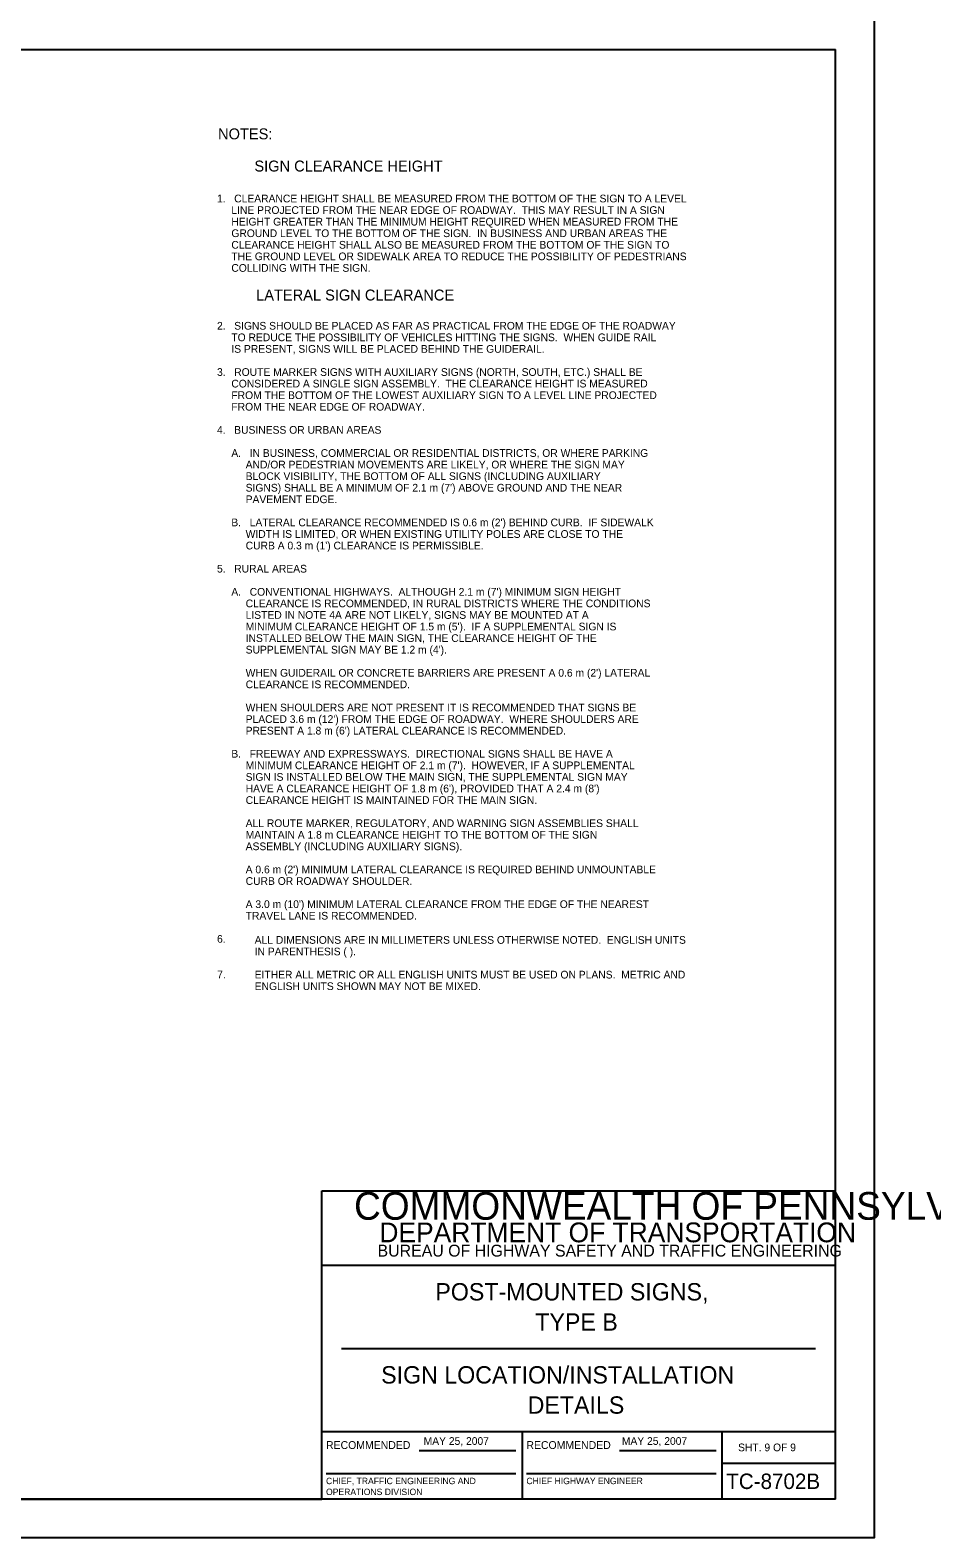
# Model space of a CAD drawing. Extents: x 644358 to 648627, y 294594 to 295782.
# Drawn here: x 647394 to 647745, y 294594 to 295180 of the extents above; entities that cross this region are included whole.
import ezdxf

# ---------------------------------------------------------------- set-up
doc = ezdxf.new("R2010")
doc.units = 0
for name, color, linetype in [('1', 7, 'Continuous'), ('2', 7, 'Continuous'), ('4', 7, 'Continuous'), ('PLT-BNDY', 7, 'Continuous')]:
    doc.layers.add(name, color=color, linetype=linetype)

msp = doc.modelspace()

# ---------------------------------------------------------------- linework, layer by layer
at = {"layer": '1'}
for p, q in [((646921.31, 295172.63), (647707.31, 295172.63)), ((647707.31, 294608.63), (647707.31, 295172.63)), ((647507.31, 294608.63), (647507.31, 294728.63)), ((647507.31, 294728.63), (647707.31, 294728.63)), ((647707.31, 294699.63), (647507.31, 294699.63)), ((647515.06, 294667.31), (647699.56, 294667.31)), ((647507.31, 294635), (647707.31, 294635)), ((647585.31, 294635), (647585.31, 294608.63)), ((647663.19, 294608.63), (647663.19, 294635)), ((647545.24, 294627.57), (647582.87, 294627.57)), ((647623.24, 294627.57), (647660.87, 294627.57)), ((647663.19, 294622.63), (647707.31, 294622.63)), ((647508.99, 294618.68), (647582.87, 294618.68)), ((647586.99, 294618.68), (647660.87, 294618.68)), ((647707.31, 294608.63), (646921.31, 294608.63)), ((646921.31, 294608.63), (647507.31, 294608.63))]:
    msp.add_line(p, q, dxfattribs=at)
at = {"layer": 'PLT-BNDY'}
msp.add_lwpolyline([(646881.31, 295187.63), (647722.31, 295187.63), (647722.31, 294593.63), (646881.31, 294593.63)], close=True, dxfattribs=at)

# ---------------------------------------------------------------- texts
at = {"layer": '1'}
for s, height, p in [('COMMONWEALTH OF PENNSYLVANIA', 10.7828, (647519.9, 294717.36)), ('DEPARTMENT OF TRANSPORTATION', 7.6837, (647529.76, 294708.61)), ('BUREAU OF HIGHWAY SAFETY AND TRAFFIC ENGINEERING', 4.6253, (647529.04, 294703.04)), ('POST-MOUNTED SIGNS,', 6.75, (647551.54, 294685.97)), ('TYPE B', 6.75, (647590.45, 294674.22)), ('SIGN LOCATION/INSTALLATION', 6.75, (647530.45, 294653.66)), ('DETAILS', 6.75, (647587.47, 294641.91)), ('RECOMMENDED', 3.048, (647508.99, 294628.2)), ('RECOMMENDED', 3.048, (647586.99, 294628.2)), ('SHT. 9 OF 9', 3, (647669.39, 294627.31)), ('CHIEF, TRAFFIC ENGINEERING AND', 2.5, (647508.99, 294614.51)), ('CHIEF HIGHWAY ENGINEER', 2.5, (647586.99, 294614.51)), ('TC-8702B', 6, (647664.77, 294612.63)), ('OPERATIONS DIVISION', 2.5, (647508.99, 294610.26))]:
    msp.add_text(s, height=height, dxfattribs=at).set_placement(p)
at = {"layer": '2'}
for s, height, p in [('NOTES:', 4.25, (647466.97, 295137.65)), ('1.   CLEARANCE HEIGHT SHALL BE MEASURED FROM THE BOTTOM OF THE SIGN TO A LEVEL', 3, (647466.56, 295113.13)), ('     LINE PROJECTED FROM THE NEAR EDGE OF ROADWAY.  THIS MAY RESULT IN A SIGN', 3, (647466.56, 295108.63)), ('     HEIGHT GREATER THAN THE MINIMUM HEIGHT REQUIRED WHEN MEASURED FROM THE', 3, (647466.56, 295104.13)), ('     GROUND LEVEL TO THE BOTTOM OF THE SIGN.  IN BUSINESS AND URBAN AREAS THE', 3, (647466.56, 295099.63)), ('     CLEARANCE HEIGHT SHALL ALSO BE MEASURED FROM THE BOTTOM OF THE SIGN TO', 3, (647466.56, 295095.13)), ('     THE GROUND LEVEL OR SIDEWALK AREA TO REDUCE THE POSSIBILITY OF PEDESTRIANS', 3, (647466.56, 295090.63)), ('     COLLIDING WITH THE SIGN.', 3, (647466.56, 295086.13)), ('2.   SIGNS SHOULD BE PLACED AS FAR AS PRACTICAL FROM THE EDGE OF THE ROADWAY', 3, (647466.56, 295063.63)), ('     TO REDUCE THE POSSIBILITY OF VEHICLES HITTING THE SIGNS.  WHEN GUIDE RAIL', 3, (647466.56, 295059.13)), ('     IS PRESENT, SIGNS WILL BE PLACED BEHIND THE GUIDERAIL.                                            ', 3, (647466.56, 295054.63)), ('3.   ROUTE MARKER SIGNS WITH AUXILIARY SIGNS (NORTH, SOUTH, ETC.) SHALL BE  ', 3, (647466.56, 295045.63)), ('     CONSIDERED A SINGLE SIGN ASSEMBLY.  THE CLEARANCE HEIGHT IS MEASURED  ', 3, (647466.56, 295041.13)), ('     FROM THE BOTTOM OF THE LOWEST AUXILIARY SIGN TO A LEVEL LINE PROJECTED ', 3, (647466.56, 295036.63)), ('     FROM THE NEAR EDGE OF ROADWAY.                                                 ', 3, (647466.56, 295032.13)), ('4.   BUSINESS OR URBAN AREAS                                               ', 3, (647466.56, 295023.13)), ('     A.   IN BUSINESS, COMMERCIAL OR RESIDENTIAL DISTRICTS, OR WHERE PARKING', 3, (647466.56, 295014.13)), ('          AND/OR PEDESTRIAN MOVEMENTS ARE LIKELY, OR WHERE THE SIGN MAY    ', 3, (647466.56, 295009.63)), ("          SIGNS) SHALL BE A MINIMUM OF 2.1 m (7') ABOVE GROUND AND THE NEAR    ", 3, (647466.56, 295000.63)), ('          BLOCK VISIBILITY, THE BOTTOM OF ALL SIGNS (INCLUDING AUXILIARY   ', 3, (647466.56, 295005.13)), ('          PAVEMENT EDGE.                                                   ', 3, (647466.56, 294996.13)), ("     B.   LATERAL CLEARANCE RECOMMENDED IS 0.6 m (2') BEHIND CURB.  IF SIDEWALK", 3, (647466.56, 294987.13)), ('          WIDTH IS LIMITED, OR WHEN EXISTING UTILITY POLES ARE CLOSE TO THE', 3, (647466.56, 294982.63)), ("          CURB A 0.3 m (1') CLEARANCE IS PERMISSIBLE.                          ", 3, (647466.56, 294978.13)), ('5.   RURAL AREAS                                                           ', 3, (647466.56, 294969.13)), ("     A.   CONVENTIONAL HIGHWAYS.  ALTHOUGH 2.1 m (7') MINIMUM SIGN HEIGHT      ", 3, (647466.56, 294960.13)), ('          CLEARANCE IS RECOMMENDED, IN RURAL DISTRICTS WHERE THE CONDITIONS', 3, (647466.56, 294955.63)), ('          LISTED IN NOTE 4A ARE NOT LIKELY, SIGNS MAY BE MOUNTED AT A      ', 3, (647466.56, 294951.13)), ("          MINIMUM CLEARANCE HEIGHT OF 1.5 m (5').  IF A SUPPLEMENTAL SIGN IS   ", 3, (647466.56, 294946.63)), ('          INSTALLED BELOW THE MAIN SIGN, THE CLEARANCE HEIGHT OF THE       ', 3, (647466.56, 294942.13)), ("          SUPPLEMENTAL SIGN MAY BE 1.2 m (4').                                 ", 3, (647466.56, 294937.63)), ("          WHEN GUIDERAIL OR CONCRETE BARRIERS ARE PRESENT A 0.6 m (2') LATERAL ", 3, (647466.56, 294928.63)), ('          CLEARANCE IS RECOMMENDED.                                        ', 3, (647466.56, 294924.13)), ('          WHEN SHOULDERS ARE NOT PRESENT IT IS RECOMMENDED THAT SIGNS BE   ', 3, (647466.56, 294915.13)), ("          PLACED 3.6 m (12') FROM THE EDGE OF ROADWAY.  WHERE SHOULDERS ARE    ", 3, (647466.56, 294910.63)), ("          PRESENT A 1.8 m (6') LATERAL CLEARANCE IS RECOMMENDED.               ", 3, (647466.56, 294906.13)), ('     B.   FREEWAY AND EXPRESSWAYS.  DIRECTIONAL SIGNS SHALL BE HAVE A', 3, (647466.56, 294897.13)), ("          MINIMUM CLEARANCE HEIGHT OF 2.1 m (7').  HOWEVER, IF A SUPPLEMENTAL", 3, (647466.56, 294892.63)), ('          SIGN IS INSTALLED BELOW THE MAIN SIGN, THE SUPPLEMENTAL SIGN MAY', 3, (647466.56, 294888.13)), ("          HAVE A CLEARANCE HEIGHT OF 1.8 m (6'), PROVIDED THAT A 2.4 m (8')", 3, (647466.56, 294883.63)), ('          CLEARANCE HEIGHT IS MAINTAINED FOR THE MAIN SIGN.                ', 3, (647466.56, 294879.13)), ('          ALL ROUTE MARKER, REGULATORY, AND WARNING SIGN ASSEMBLIES SHALL', 3, (647466.56, 294870.13)), ('          ASSEMBLY (INCLUDING AUXILIARY SIGNS).                           ', 3, (647466.56, 294861.13)), ('          MAINTAIN A 1.8 m CLEARANCE HEIGHT TO THE BOTTOM OF THE SIGN    ', 3, (647466.56, 294865.63)), ("          A 0.6 m (2') MINIMUM LATERAL CLEARANCE IS REQUIRED BEHIND UNMOUNTABLE", 3, (647466.56, 294852.13)), ('          CURB OR ROADWAY SHOULDER.                                       ', 3, (647466.56, 294847.63)), ("          A 3.0 m (10') MINIMUM LATERAL CLEARANCE FROM THE EDGE OF THE NEAREST", 3, (647466.56, 294838.63)), ('          TRAVEL LANE IS RECOMMENDED.', 3, (647466.56, 294834.13)), ('6.   ', 3, (647466.56, 294825.13)), ('MAY 25, 2007', 3, (647546.98, 294629.79)), ('MAY 25, 2007', 3, (647624.14, 294629.79))]:
    msp.add_text(s, height=height, dxfattribs=at).set_placement(p)
at = {"layer": '4'}
for s, height, p in [('SIGN CLEARANCE HEIGHT', 4.25, (647481.11, 295125.14)), ('LATERAL SIGN CLEARANCE', 4.25, (647481.79, 295074.96)), ('ALL DIMENSIONS ARE IN MILLIMETERS UNLESS OTHERWISE NOTED.  ENGLISH UNITS', 3, (647481.21, 294824.72)), ('IN PARENTHESIS ( ).', 3, (647481.21, 294820.22)), ('7.', 3, (647466.61, 294811.27)), ('EITHER ALL METRIC OR ALL ENGLISH UNITS MUST BE USED ON PLANS.  METRIC AND', 3, (647481.21, 294811.22)), ('ENGLISH UNITS SHOWN MAY NOT BE MIXED.', 3, (647481.21, 294806.72))]:
    msp.add_text(s, height=height, dxfattribs=at).set_placement(p)

doc.saveas('drawing.dxf')
